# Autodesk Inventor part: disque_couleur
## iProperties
Created: 2011-01
Part Number: disque_couleur
Document SubType Name: Modeling
Designer: eric
Density: 1 g/cm^3
Mass: 3.09074 g
Surface Area: 80.1728 cm^2
Volume: 3.09074 cm^3
Author: eric
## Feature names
1. Base1
